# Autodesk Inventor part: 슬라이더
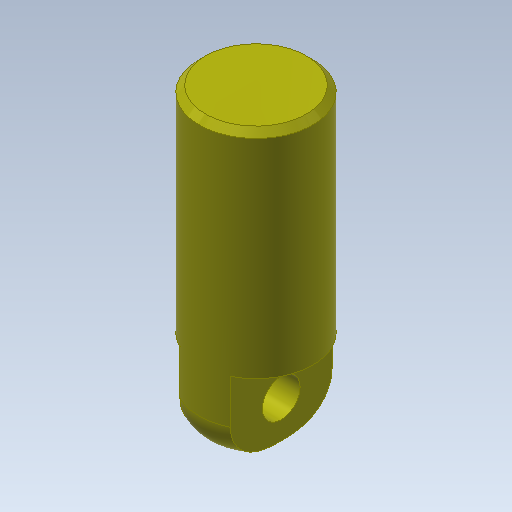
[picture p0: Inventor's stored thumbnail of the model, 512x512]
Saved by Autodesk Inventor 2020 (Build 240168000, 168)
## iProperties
Created: 2016-08
Part Number: 슬라이더
Material: 강철, 탄소
Document SubType Name: Modeling
Designer: mduedu
Density: 7.87 g/cm^3
Appearance: 노란색
Author: mduedu
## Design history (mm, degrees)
sketch "스케치1"
  geometry: C1 r 9 at (0, 0); 1 further point
  constraints: 1 centre point, 1 coincident
  dimensions: "d0" = 18 diameter of C1
extrude "돌출1" new body sketch "스케치1" distance "d1" = 47; taper "d2" = 0 deg
fillet "모깎기1" dims "d21" = 6
sketch "스케치6"
  geometry: L1 (9, 6)-(9, 47) reference; L2 (-9, 6)-(-9, 47) reference; L3 (9, 47)-(-9, 47) reference; L4 (0, 47)-(0, 0); L5 (9, 13)-(4, 13); L6 (4, 13)-(4, 0); L7 (4, 0)-(9, 0); L8 (9, 0)-(9, 13); L9 (-9, 13)-(-4, 13); L10 (-4, 13)-(-4, 0); L11 (-4, 0)-(-9, 0); L12 (-9, 0)-(-9, 13)
  constraints: 18 end point, 4 symmetric about line, 2 parallel, 2 perpendicular, 1 horizontal, 1 horizontal alignment, 1 midpoint, 1 point on line
  dimensions: "d22" = 13 distance of L7.end L5.start; "d24" = 4 distance between parallel lines of L6 L4
extrude "돌출5" cut sketch "스케치6" extent not by distance; stored distance "d25" = 8; taper "d26" = 0 deg
sketch "스케치8"
  geometry: C1 r 3 at (6, 0); 1 further point
  constraints: 1 centre point, 1 horizontal alignment
  dimensions: "d27" = 6 diameter of C1; "d28" = 6 distance of point (0, 0) C1.centre
extrude "돌출6" cut sketch "스케치8" extent not by distance; stored distance "d29" = 8; taper "d30" = 0 deg
chamfer "모따기2" distance "d43" = 1; stored, may be unused: second distance "d44" = 2, angle "d45" = 30 deg
node "솔리드1"
